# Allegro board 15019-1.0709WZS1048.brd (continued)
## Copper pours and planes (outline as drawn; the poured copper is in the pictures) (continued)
PWR_GFX_SW1 on BOTTOM: 54.77,210.95 54.64,211.07 54.64,215.39 54.39,215.65 52.74,215.65 52.61,215.77 52.61,217.04 52.74,217.17 54.64,217.17 54.9,217.42 54.9,221.11 55.15,221.36 67.34,221.36 67.47,221.23 67.47,215.26 63.15,210.95
PWR_VDDP_BOOT on TOP: 19.77,157.68 19.77,158.85 21.72,160.81 23.05,160.81 23.38,160.48 23.38,159.87 23.2,159.69 22.72,159.69 20.71,157.68
PWR_VDDP_PHASE on TOP: 29.62,149.22 29.5,149.35 29.5,154.56 29.75,154.81 32.8,154.81 33.31,155.32 33.31,161.54 33.56,161.8 37.24,161.8 38.26,160.78 38.26,152.65 34.83,149.22 ; 2 cut-outs
PWR_VDDP_SNB on TOP: 30.77,155.19 30.64,155.32 30.64,157.1 30.77,157.23 32.93,157.23 33.05,157.1 33.05,155.32 32.93,155.19 ; 1 cut-out
PWR_VDDQ_PHASE on TOP: 142.73,79.45 142.73,80.59 143.85,81.71 144.51,81.71 144.71,81.51 144.71,81.13 143.04,79.45
PWR_VDDQ_PHASE on TOP: 140.5,91.95 140.37,92.08 140.37,95.63 140.24,95.76 135.42,95.76 135.29,95.89 135.29,99.06 136.69,100.46 142.78,100.46 145.96,97.28 145.96,92.08 145.83,91.95
PWR_VDDQ_VTTIN on TOP: 141.54,79.45 141.51,79.48 141.51,80.26 139.76,82.02 136.76,82.02 136.46,82.32 136.46,83.85 136.53,83.92 142.07,83.92 142.12,83.87 142.12,82.5 141.31,81.69 141.31,80.98 141.71,80.57 141.71,79.48 141.69,79.45
SB3V on TOP: 86.52,7.11 86.39,7.24 86.39,10.54 86.52,10.67 88.3,10.67 88.81,11.18 89.57,11.18 89.82,10.92 89.82,9.78 89.06,9.02 89.06,7.37 88.81,7.11 ; 2 cut-outs
SB3V on TOP: 80.83,87.22 80.6,87.45 80.6,88.49 80.7,88.6 82.63,88.6 82.81,88.42 82.81,87.53 82.51,87.22 ; 1 cut-out
SB3V on TOP: 128.99,55.22 128.4,55.8 128.4,57.35 124.11,61.65 124.11,65.66 128.18,69.72 144.53,69.72 145.65,70.84 145.65,72.34 145.75,72.44 146.41,72.44 146.79,72.06 146.79,69.88 148.04,68.63 149.74,68.63 150.53,67.84 150.53,65.41 150.25,65.13 150.25,64.57 150.12,64.44 149.72,64.44 149.59,64.57 149.59,65.79 148.72,66.65 146.06,66.65 145.19,65.79 145.19,64.52 145.07,64.39 143.42,64.39 143.04,64.77 141.89,64.77 141.64,65.02 141.64,65.91 140.67,66.88 136.1,66.88 134.73,65.51 133.31,65.51 133.03,65.23 130.23,65.23 129.24,64.24 129.24,59.28 129.95,58.57 129.95,56.72 130.23,56.44 130.23,55.37 130.08,55.22 ; 4 cut-outs
SB3V on TOP: 117.79,103.76 117.58,103.96 117.58,104.88 117.86,105.16 118.83,105.16 119.13,105.46 120.45,105.46 120.56,105.36 120.56,103.84 120.48,103.76
SB3V on BOTTOM: 40.8,4.32 39.28,5.84 39.28,7.62 39.53,7.87 40.42,7.87 41.94,6.35 41.94,4.57 41.69,4.32 ; 2 cut-outs
SB3V on BOTTOM: 162.52,187.12 162.01,187.63 162.01,197.03 161.3,197.74 161.3,199.47 163.91,199.47 165.39,197.99 165.39,188.01 164.5,187.12 ; 2 cut-outs
SB3V on BOTTOM: 125.26,206.25 125,206.5 125,209.8 126.27,211.07 127.54,211.07 128.3,210.31 128.3,208.03 128.43,207.9 130.08,207.9 130.34,207.65 130.34,206.38 130.21,206.25 ; 6 cut-outs
SB5V on TOP: 91.6,7.24 91.47,7.37 91.47,9.14 90.97,9.65 90.97,11.05 91.09,11.18 91.6,11.18 91.98,10.79 93.89,10.79 94.39,10.29 94.39,7.49 94.14,7.24 ; 3 cut-outs
SB5V on BOTTOM: 146.59,52.2 146.46,52.32 146.46,54.48 146.72,54.74 147.99,54.74 148.12,54.61 148.12,52.32 147.99,52.2
USBVCC01 on TOP: 100.62,16.76 100.36,17.02 100.36,28.75 100.74,29.13 101.63,29.13 102.01,29.51 102.01,38.86 101.76,39.12 100.24,39.12 99.86,39.5 99.86,41.4 100.49,42.04 104.81,42.04 104.94,41.91 104.94,29.72 105.19,29.46 105.82,29.46 105.95,29.34 105.95,27.81 106.08,27.69 108.11,27.69 108.24,27.56 108.24,19.43 107.86,19.05 105.06,19.05 104.94,19.18 104.94,23.11 104.81,23.24 103.41,23.24 103.28,23.11 103.28,17.02 103.03,16.76 ; 3 cut-outs
USBVCC23 on TOP: 169.96,119.63 169.45,120.14 169.45,125.48 169.58,125.6 173.13,125.6 173.64,125.09 173.64,120.02 173.26,119.63 ; 3 cut-outs
USBVCC23 on L3: 165.51,116.46 165.51,99.11 166.24,98.39 168.7,98.39 169.17,97.92 173.26,97.92 173.77,98.42 173.77,111.38 171.99,113.16 171.99,117.86 173.77,119.63 173.77,121.03 173.52,121.28 170.34,121.28
USBVCCTP on TOP: 29.12,4.7 28.66,5.16 26.45,5.16 26.09,5.51 26.09,7.06 26.27,7.24 26.93,7.24 27.34,6.83 29.78,6.83 30.13,6.48 30.13,5.08 29.75,4.7
USBVCCTP on BOTTOM: 24.8,5.33 24.67,5.46 24.67,9.02 24.8,9.14 27.21,9.14 27.47,8.89 27.47,8 26.96,7.49 26.96,5.46 26.83,5.33
V_1P05_LAN on BOTTOM: 34.32,9.83 33.51,10.64 33.51,13.56 34.73,14.78 35.75,14.78 35.97,14.55 35.97,12.65 36.23,12.4 38.41,12.4 38.44,12.37 38.44,11.53 39.07,10.9 39.73,10.9 40.55,11.71 40.55,16.51 40.42,16.64 40.42,17.65 40.55,17.78 41.31,17.78 41.92,17.17 41.92,11.61 40.14,9.83 ; 8 cut-outs
V_1P5_PWR on TOP: 32.16,142.88 31.66,143.38 29.88,143.38 29.24,144.02 27.72,144.02 27.47,144.27 27.47,146.3 27.85,146.69 33.84,146.69 34.15,146.38 34.15,145.92 33.43,145.21 33.43,143 33.31,142.88 ; 6 cut-outs
V_1P8_VDDIO on TOP: 24.42,141.99 24.29,142.11 24.29,145.16 24.04,145.41 22.39,145.41 22.13,145.67 22.13,148.34 22.26,148.46 25.56,148.46 27.34,146.69 27.34,142.11 27.21,141.99
V_3_CARD_BD on TOP: 159.55,143 159.42,143.13 159.42,146.18 159.55,146.3 167.67,146.3 167.8,146.18 167.8,143.13 167.67,143 ; 8 cut-outs
V_3P0_BAT_VREG on TOP: 156.62,120.65 156.5,120.78 156.5,122.94 156.62,123.06 159.67,123.06 159.8,122.94 159.8,120.78 159.67,120.65 ; 4 cut-outs
V_3P3_A on TOP: 88.68,12.45 88.17,12.95 87.66,12.95 87.54,13.08 87.54,16.76 87.79,17.02 88.93,17.02 89.19,16.76 89.19,15.88 89.57,15.49 89.57,13.34 89.7,13.21 89.7,12.57 89.57,12.45 ; 5 cut-outs
V_3P3_A on TOP: 138.08,3.43 137.83,3.68 137.83,5.18 137.75,5.26 136.25,5.26 135.42,6.1 130.59,6.1 130.46,6.22 130.46,12.32 130.59,12.45 132.88,12.45 136.3,9.02 140.24,9.02 140.37,8.89 140.37,5.33 140.5,5.21 142.15,5.21 142.27,5.33 142.27,5.71 142.4,5.84 143.54,5.84 144.05,6.35 144.94,6.35 145.19,6.1 145.19,5.59 145.32,5.46 145.7,5.46 145.83,5.33 145.83,4.45 144.81,3.43 ; 3 cut-outs
V_3P3_A on L3: 136.81,2.03 89.19,2.03 88.17,3.05 88.17,4.95 88.3,5.08 89.82,5.08 90.58,4.32 135.92,4.32 136.94,5.33 136.94,8.76 137.19,9.02 139.23,9.02 139.61,8.64 139.61,4.83
V_3P3_A on L4: 87.92,16 87.66,15.75 87.66,12.06 87.03,11.43 87.03,7.62 87.54,7.11 87.54,5.08 87.92,4.7 87.92,3.56 88.17,3.3 89.44,3.3 89.7,3.56 92.49,3.56 93.25,4.32 93.25,14.86 92.11,16
V_3P3_LAN on L3: 37.93,6.12 30.92,6.12 29.37,7.67 29.37,9.91 30.04,10.58 31.36,10.58 37.75,16.97 37.75,17.63 38.34,18.21 39.23,18.21 41.46,15.98 41.46,9.65
V_3P3_PCIVAUX on TOP: 117.64,222.25 117.51,222.38 117.51,223.14 120.18,225.81 121.7,225.81 121.95,225.55 121.95,224.28 121.83,224.16 121.45,224.16 119.54,222.25 ; 1 cut-out
V_3P3_PCIVAUX on TOP: 117.51,202.95 117.38,203.07 117.38,205.61 117.51,205.74 121.57,205.74 121.95,205.36 121.95,203.2 121.7,202.95 ; 2 cut-outs
V_3P3_PCIVAUX on BOTTOM: 121.95,202.44 121.32,203.07 121.32,205.61 121.45,205.74 132.37,205.74 132.49,205.61 132.49,202.69 132.24,202.44 ; 6 cut-outs
V_3P3_PCIVAUX on L3: 120.94,202.69 121.06,202.56 122.21,202.56 122.33,202.69 122.33,205.74 122.21,205.87 121.06,205.87 120.94,205.74
V_5_LCD1 on BOTTOM: 34.32,106.65 34.07,106.91 33.92,106.91 33.59,107.24 32.82,107.24 32.8,107.26 32.8,108.61 32.88,108.69 35.24,108.69 35.72,108.2 35.72,106.76 35.62,106.65 ; 1 cut-out
V_5_LCD2 on BOTTOM: 36.48,106.55 36.36,106.68 36.36,109.22 36.86,109.73 38.26,109.73 38.39,109.6 38.39,108.84 39.15,108.08 39.15,106.68 39.02,106.55 ; 2 cut-outs
V_5HDD on BOTTOM: 4.86,191.13 4.73,191.26 4.73,196.6 5.88,197.74 5.88,201.73 5.98,201.83 13.47,201.83 13.62,201.68 13.62,193.78 13.39,193.55 10.57,193.55 8.16,191.13 ; 4 cut-outs
V_5P0_A on TOP: 130.59,16.51 130.46,16.64 130.46,22.61 130.72,22.86 135.42,22.86 136.43,23.88 138.34,23.88 138.72,23.5 138.72,20.07 138.59,19.94 136.18,19.94 132.75,16.51 ; 2 cut-outs
V_5P0_A on TOP: 144.13,7.75 144.13,7.8 143.31,8.61 143.31,9.3 143.54,9.53 144.31,9.53 144.91,8.92 144.91,7.8 144.86,7.75
V_5P0_A on TOP: 97.23,10.91 95.26,12.88 92.03,12.88 91.68,12.52 90.25,12.52 90.2,12.57 90.2,13.61 90.1,13.72 90.1,14.05 90.94,14.88 95.44,14.88 98.31,12.01 98.31,11.63 97.58,10.91 ; 2 cut-outs
V_5P0_A on TOP: 85.76,30.35 84.49,31.62 84.49,33.27 84.5,33.29 84.5,34.48 85.55,35.53 90.13,35.53 91.47,34.19 91.47,30.48 91.35,30.35
V_5P0_A on BOTTOM: 87.69,31.11 86.11,32.69 86.11,34.95 86.39,35.23 89.26,35.23 89.7,34.8 89.7,31.37 89.44,31.11
V_5P0_A on BOTTOM: 140.88,7.11 139.35,8.64 139.35,10.54 136.94,12.95 136.94,23.24 137.07,23.37 139.73,23.37 139.86,23.24 139.86,13.84 144.69,9.02 144.69,7.37 144.43,7.11
V_5P0_HDMI_CONN on TOP: 107.6,34.16 107.48,34.29 107.48,35.94 107.22,36.2 107.22,40.39 108.75,41.91 114.84,41.91 114.97,41.78 114.97,40.89 114.84,40.77 109.13,40.77 108.75,40.39 108.75,34.29 108.62,34.16 ; 2 cut-outs
V_19_INV on TOP: 43.39,37.59 43.26,37.72 43.26,49.12 43.31,49.17 43.31,50.77 43.85,51.31 47.53,51.31 47.79,51.05 47.79,50.15 48.29,49.65 50.2,49.65 50.33,49.53 50.33,48.01 49.82,47.5 49.82,41.78 49.31,41.27 47.38,41.27 46.52,40.41 46.52,37.72 46.39,37.59 ; 1 cut-out
VOUT_INV on TOP: 26.32,37.72 25.69,38.35 25.69,41.78 27.72,43.81 35.62,43.81 36.41,43.03 36.41,41.66 37.6,40.46 37.6,39.88 37.35,39.62 33.05,39.62 32.29,40.39 32.29,41.53 31.91,41.91 27.59,41.91 27.21,41.53 27.21,39.88 27.59,39.5 30.89,39.5 31.02,39.37 31.02,37.97 30.77,37.72
VOUT_INV on BOTTOM: 27.52,34.72 27.31,34.92 27.31,36.4 27.21,36.5 27.21,42.55 27.47,42.8 36.61,42.8 37.24,42.16 37.24,40.59 37.7,40.13 37.7,39.75 37.5,39.55 36.94,39.55 36.89,39.5 36.89,39.37 34.96,39.37 34.2,38.61 32.29,38.61 30.64,36.96 30.64,34.95 30.41,34.72

Small or netless copper shapes (teardrops, artwork), in the pictures only: 5 on TOP, 5 on BOTTOM

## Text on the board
Ref Des/Silkscreen Bottom: F2:2A/6V | F15:1.5A/6V | F3:1.5A/6V | F1:1.5A/6V | F5:2A/6V | LAN ID
Ref Des/Silkscreen Top: NORMAL(DEFAULT) | 1-2 | CLR PASSWORD | NC | CLR CMOS | J01010 | SATA HDD | TOUCH | BATTERY | PWRCN1 | F16:3A/32V | F12:2A/6V | F13:1.5A/6V | RJ1 | X4:25MHZ | USB3 | NGFF_WIFI | Rev:A00 | SPEAKER | SSUSB2 | SSUSB1 | UHS1 | FAN_CPU | SATAP1 | CONVERTER | LVDS | X1:48MHZ | X54:30MHZ | DCIN1 | CPU1 | LOUT1 | USB4 | DIMM1 | PSWD | RTCRST | DIMM2 | F14:2A/6V | For DDR3L Only | F6:1.5A/6V | WEBCAM | M | A | J | H | F | M2 | Carrizo L AIO eMMC | 15019-1 | YNC24 | MADE IN TAIWAN
User.27: Board Accuracy Check,Jul 09 10:11:03 2015,Passed | Dummy-Static-No Shape On Layer Check,Jul 09 10:11:03 2015,Passed | Split Plane Check,Mar 30 10:33:00 2015,Passed
User.31: GND | AGND | 1D35V_S3
User.33: ByImpedance:100.0@_REF_L1=("3.5/10.0(L1)")|_REF_L6=("3.5/10.0(L6)")|Type="DP"|_REF_L4=("4.0/9.0(L4)")|_REF_L3=("4.0/9.0(L3)")|imp="100.0" | ByImpedance:110.0@_REF_L1=("nil(L1)")|_REF_L6=("nil(L6)")|Type="DP"|_REF_L4=("3.5/13.0(L4)")|_REF_L3=("3.5/13.0(L3)")|imp="110.0" | ByImpedance:27.4@_REF_L1=("12.0(L1)")|_REF_L6=("12.0(L6)")|Type="SE"|_REF_L4=("16.0(L4)")|_REF_L3=("16.0(L3)")|imp="27.4" | ByImpedance:33.0@_REF_L1=("9.0(L1)")|_REF_L6=("9.0(L6)")|Type="SE"|_REF_L4=("12.0(L4)")|_REF_L3=("12.0(L3)")|imp="33.0" | ByImpedance:34.0@_REF_L1=("8.5(L1)")|_REF_L6=("8.5(L6)")|Type="SE"|_REF_L4=("11.5(L4)")|_REF_L3=("11.5(L3)")|imp="34.0" | ByImpedance:35.0@_REF_L1=("8.0(L1)")|_REF_L6=("8.0(L6)")|Type="SE"|_REF_L4=("10.5(L4)")|_REF_L3=("10.5(L3)")|imp="35.0" | ByImpedance:37.5@_REF_L1=("7.0(L1)")|_REF_L6=("7.0(L6)")|Type="SE"|_REF_L4=("9.5(L4)")|_REF_L3=("9.5(L3)")|imp="37.5" | ByImpedance:39.0@_REF_L1=("6.5(L1)")|_REF_L6=("6.5(L6)")|Type="SE"|_REF_L4=("9.0(L4)")|_REF_L3=("9.0(L3)")|imp="39.0" | ByImpedance:40.0@_REF_L1=("6.5(L1)")|_REF_L6=("6.5(L6)")|Type="SE"|_REF_L4=("8.5(L4)")|_REF_L3=("8.5(L3)")|imp="40.0" | ByImpedance:42.0@_REF_L1=("5.5(L1)")|_REF_L6=("5.5(L6)")|Type="SE"|_REF_L4=("7.5(L4)")|_REF_L3=("7.5(L3)")|imp="42.0" | ByImpedance:45.0@_REF_L1=("5.0(L1)")|_REF_L6=("5.0(L6)")|Type="SE"|_REF_L4=("6.5(L4)")|_REF_L3=("6.5(L3)")|imp="45.0" | ByImpedance:48.0@_REF_L1=("4.5(L1)")|_REF_L6=("4.5(L6)")|Type="SE"|_REF_L4=("5.5(L4)")|_REF_L3=("5.5(L3)")|imp="48.0" | ByImpedance:50.0@_REF_L1=("4.0(L1)")|_REF_L6=("4.0(L6)")|Type="SE"|_REF_L4=("5.0(L4)")|_REF_L3=("5.0(L3)")|imp="50.0" | ByImpedance:52.0@_REF_L1=("3.5(L1)")|_REF_L6=("3.5(L6)")|Type="SE"|_REF_L4=("4.5(L4)")|_REF_L3=("4.5(L3)")|imp="52.0" | ByImpedance:55.0@_REF_L1=("nil(L1)")|_REF_L6=("nil(L6)")|Type="SE"|_REF_L4=("4.0(L4)")|_REF_L3=("4.0(L3)")|imp="55.0" | ByImpedance:65.0@_REF_L1=("8.0/6.0(L1)")|_REF_L6=("8.0/6.0(L6)")|Type="DP"|_REF_L4=("9.0/5.0(L4)")|_REF_L3=("9.0/5.0(L3)")|imp="65.0" | ByImpedance:68.0@_REF_L1=("6.5/4.0(L1)")|_REF_L6=("6.5/4.0(L6)")|Type="DP"|_REF_L4=("7.5/4.0(L4)")|_REF_L3=("7.5/4.0(L3)")|imp="68.0" | ByImpedance:70.0@_REF_L1=("7.0/6.0(L1)")|_REF_L6=("7.0/6.0(L6)")|Type="DP"|_REF_L4=("8.0/6.0(L4)")|_REF_L3=("8.0/6.0(L3)")|imp="70.0" | ByImpedance:72.0@_REF_L1=("7.0/8.0(L1)")|_REF_L6=("7.0/8.0(L6)")|Type="DP"|_REF_L4=("7.0/5.0(L4)")|_REF_L3=("7.0/5.0(L3)")|imp="72.0" | ByImpedance:75.0@_REF_L1=("6.0/6.0(L1)")|_REF_L6=("6.0/6.0(L6)")|Type="DP"|_REF_L4=("7.0/6.0(L4)")|_REF_L3=("7.0/6.0(L3)")|imp="75.0" | ByImpedance:80.0@_REF_L1=("5.0/5.0(L1)")|_REF_L6=("5.0/5.0(L6)")|Type="DP"|_REF_L4=("6.0/6.0(L4)")|_REF_L3=("6.0/6.0(L3)")|imp="80.0" | ByImpedance:85.0@_REF_L1=("5.0/8.0(L1)" "4.0/4.5(L1)")|_REF_L6=("5.0/8.0(L6)" "4.0/4.5(L6)")|Type="DP"|_REF_L4=("5.0/5.5(L4)")|_REF_L3=("5.0/5.5(L3)")|imp="85.0" | ByImpedance:90.0@_REF_L1=("4.0/6.0(L1)")|_REF_L6=("4.0/6.0(L6)")|Type="DP"|_REF_L4=("5.0/8.0(L4)" "4.0/5.0(L4)")|_REF_L3=("5.0/8.0(L3)" "4.0/5.0(L3)")|imp="90.0" | ByImpedance:93.0@_REF_L1=("4.0/8.0(L1)" "3.5/5.5(L1)")|_REF_L6=("4.0/8.0(L6)" "3.5/5.5(L6)")|Type="DP"|_REF_L4=("5.0/9.0(L4)" "4.0/5.5(L4)")|_REF_L3=("5.0/9.0(L3)" "4.0/5.5(L3)")|imp="93.0" | ByImpedance:95.0@_REF_L1=("4.0/10.0(L1)" "3.5/6.0(L1)")|_REF_L6=("4.0/10.0(L6)" "3.5/6.0(L6)")|Type="DP"|_REF_L4=("4.0/6.5(L4)")|_REF_L3=("4.0/6.5(L3)")|imp="95.0" | LayerIndex:nil | Source:6-1.2-7c.xls | artWorks:("_REF_L3" "_REF_L4" "_REF_L6" "_REF_L1") | gtImpOutlineUsed:BOARD GEOMETRY/PANEL_OUTLINE
User.34: GND | AGND | 1D35V_S3
User.35: 1 | Factory ID:J | CONVERTER | CPU1 | DCIN1 | DIMM1 | Dell: | F15:1.5A/6V | F16:3A/32V | F6:1.5A/6V | LOUT1 | LVDS | NGFF_WIFI | PSWD | PWRCN1 | SATA HDD | SATA ODD | SATAP1 | SPEAKER | SSUSB1 | SSUSB2 | TOUCH | UHS1 | USB3 | USB4 | WEBCAM | X1:48MHZ | X2:32.768KHZ | X4:25MHZ | A | B | C | E | H | J | M | N | P | 14050-SC | 348.02001.00SC | Carrizo AIO | F | MADE IN TAIWAN
User.39: This gerber is just for your reference to find the DP impedance traces in layer L1. | DP IMPEDANCE TABLE: L1 | * - Denotes that WIDTH | is NOT used in this layer | inside board outline. | IMP(Ohm) | 65.0 | 68.0 | 70.0 | 72.0 | 75.0 | 80.0 | 85.0 | 90.0 | 93.0 | 95.0 | 100.0 | 110.0 | WIDTH(mils) | *8.0/6.0 | *6.5/4.0 | *7.0/6.0 | 7.0/8.0 | *6.0/6.0 | 5.0/5.0 | *5.0/8.0 | 4.0/4.5 | 4.0/6.0 | 4.0/8.0 | *3.5/5.5 | *4.0/10.0 | *3.5/6.0 | 3.5/10.0 | *nil | TYPE | DP
User.41: This gerber is just for your reference to find the SE impedance traces in layer L1. | SE IMPEDANCE TABLE: L1 | * - Denotes that WIDTH | is NOT used in this layer | inside board outline. | IMP(Ohm) | 27.4 | 33.0 | 34.0 | 35.0 | 37.5 | 39.0 | 40.0 | 42.0 | 45.0 | 48.0 | 50.0 | 52.0 | 55.0 | WIDTH(mils) | 12.0 | *9.0 | *8.5 | 8.0 | *7.0 | 6.5 | *5.5 | 5.0 | *4.5 | 4.0 | 3.5 | *nil | TYPE | SE
User.43: This gerber is just for your reference to find the DP impedance traces in layer L3. | DP IMPEDANCE TABLE: L3 | * - Denotes that WIDTH | is NOT used in this layer | inside board outline. | IMP(Ohm) | 65.0 | 68.0 | 70.0 | 72.0 | 75.0 | 80.0 | 85.0 | 90.0 | 93.0 | 95.0 | 100.0 | 110.0 | WIDTH(mils) | *9.0/5.0 | *7.5/4.0 | *8.0/6.0 | 7.0/5.0 | *7.0/6.0 | 6.0/6.0 | 5.0/5.5 | *5.0/8.0 | 4.0/5.0 | *5.0/9.0 | *4.0/5.5 | *4.0/6.5 | 4.0/9.0 | *3.5/13.0 | TYPE | DP
User.45: This gerber is just for you reference to find the differential traces in layer BOTTOM | This gerber is just for you reference to find the differential traces in layer L3 | This gerber is just for you reference to find the differential traces in layer L4 | This gerber is just for you reference to find the differential traces in layer TOP | Note:Refer to DRILL layer for ELLIPSE drill direction | FIGURE | SIZE | 8.0 | 10.0 | 12.0 | 16.0 | 20.0 | 28.0 | 30.0 | 36.0 | 37.0 | 39.0 | 40.0 | 60.0 | 91.0 | 109.0 | 158.0 | 42.0 | 44.0 | 50.0 | 54.0 | 63.0 | 67.0 | 86.0 | 138.0 | 178.0 | 48.0x16.0 | 56.0x24.0 | 60.0x24.0 | 60.0x28.0 | 67.0x28.0 | 67.0x30.0 | 67.0x32.0 | 91.0x28.0 | 156.0x32.0 | 166.0x32.0 | 197.0x178.0 | DRILL CHART: TOP to BOTTOM | ALL UNITS ARE IN MILS | PLATED | NON-PLATED | QTY | 16 | 864 | 2475 | 867 | 40 | 18 | 7 | 8 | 30 | 9 | 2 | 4 | 1 | 5 | 3 | 6 | This gerber is just for your reference to find the DP impedance traces in layer L4. | This gerber is just for your reference to find the DP impedance traces in layer L6. | This gerber is just for your reference to find the SE impedance traces in layer L3. | This gerber is just for your reference to find the SE impedance traces in layer L4. | This gerber is just for your reference to find the SE impedance traces in layer L6. | DP IMPEDANCE TABLE: L4 | DP IMPEDANCE TABLE: L6 | SE IMPEDANCE TABLE: L3 | SE IMPEDANCE TABLE: L4 | SE IMPEDANCE TABLE: L6 | * - Denotes that WIDTH | is NOT used in this layer | inside board outline. | Model | Carrizo L AIO eMMC  829777 | ECO | PCB_NO | 15019 | VER. | Layer | DRILL | L1 | L2GND | L3 | TMASK | TPLACE | TSILK | TSMD | Designer | BRUCE | IMP(Ohm) | 27.4 | 65.0 | 33.0 | 68.0 | 34.0 | 70.0 | 35.0 | 72.0 | 37.5 | 75.0 | 80.0 | 85.0 | 90.0 | 45.0 | 48.0 | 93.0 | 52.0 | 95.0 | 100.0 | 55.0 | 110.0 | Date | 07/09/2015 | WIDTH(mils) | *16.0 | *12.0 | *9.0 | *11.5 | *8.5 | *10.5 | 10.5 | *7.0 | *9.5 | 6.5 | 8.5 | *5.5 | *7.5 | 5.0 | *4.5 | 4.0 | *3.5 | *nil | *8.0/6.0 | *9.0/5.0 | *6.5/4.0 | *7.5/4.0 | *7.0/6.0 | *7.0/5.0 | *7.0/8.0 | *6.0/6.0 | 5.0/5.0 | 6.0/6.0 | *5.0/8.0 | 5.0/5.5 | 4.0/4.5 | 4.0/5.0 | 4.0/6.0 | *4.0/8.0 | *5.0/9.0 | *3.5/5.5 | *4.0/5.5 | *4.0/10.0 | *4.0/6.5 | *3.5/6.0 | 4.0/9.0 | *3.5/13.0 | 3.5/10.0 | TYPE | SE | DP | BMASK | BPLACE | BSILK | BSMD | L4 | L5GND | L6
